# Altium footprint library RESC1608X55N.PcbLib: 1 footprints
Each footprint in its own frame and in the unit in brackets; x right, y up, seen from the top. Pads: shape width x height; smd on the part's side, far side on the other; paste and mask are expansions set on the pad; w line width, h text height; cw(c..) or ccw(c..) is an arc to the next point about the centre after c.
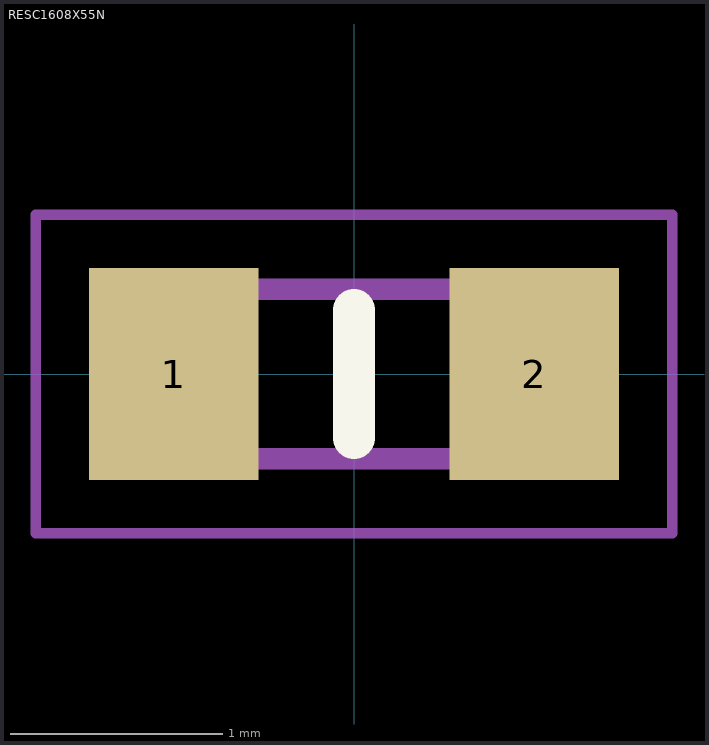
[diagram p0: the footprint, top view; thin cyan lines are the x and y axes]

## RESC1608X55N [mm]
pads (2):
  rect 0.8x1 smd: 1(-0.85,0) 2(0.85,0)
Top Overlay:
  lines w0.2: 0,-0.3 0,0.3
Mechanical 15:
  lines w0.1: -0.8,-0.4 0.8,-0.4 0.8,0.4 -0.8,0.4 -0.8,-0.4
Mechanical 20:
  lines w0.05: -1.5,-0.75 1.5,-0.75 1.5,0.75 -1.5,0.75 -1.5,-0.75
